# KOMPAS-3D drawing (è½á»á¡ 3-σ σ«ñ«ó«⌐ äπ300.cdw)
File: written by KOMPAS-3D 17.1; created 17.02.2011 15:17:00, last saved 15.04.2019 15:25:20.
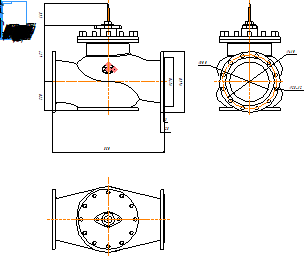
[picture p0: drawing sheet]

Title block, sheet 1: name: Клапан 3-х ходовой Ду300; material: Внимание! Данный продукт является объектом авторского права ООО «Торговый Дом АДЛ». / Запрещается изменение, копирование, распространение / (в том числе путем копирования на другие сайты и ресурсы в Интернете) / или любое иное использование информации и объектов без предварительного / согласия правообладателя (ООО «Торговый Дом АДЛ»).; scale: 1:1; sheets: 1; organisation: ООО "Торговый дом АДЛ"; sheet format: A4; stored path: \\adlc.lan\data\АДЛ_ПКД\3D-модели\ADL production\Клапаны ГРАНРЕГ\Трёхходовой клапан КМ307Ф\KOMPAS 2D\Клапан 3-х ходовой Ду300.cdw

Views: Спереди 1, Проекционный вид 2, Проекционный вид 3
Dimensions and other numbers on the sheet: 427; 220; 850; 3; 28; 370; 460; 410; 300; 165; 1:1; 1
